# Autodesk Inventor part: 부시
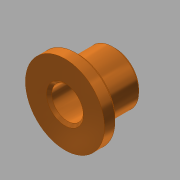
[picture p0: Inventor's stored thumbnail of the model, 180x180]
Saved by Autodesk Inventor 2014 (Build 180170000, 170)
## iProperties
Created: 2016-02
Part Number: 부시
Material: 스테인리스강
Document SubType Name: Modeling
Designer: mduedu
Density: 8.08 g/cm^3
Appearance: 금속 1600F 열
Mass: 45.9536 g
Surface Area: 31.3929 cm^2
Volume: 5.68733 cm^3
Author: mduedu
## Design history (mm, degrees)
sketch "스케치1"
  geometry: C1 r 15 at (0, 0); 1 further point
  constraints: 1 centre point, 1 coincident
  dimensions: "d0" = 30 diameter of C1
extrude "돌출1" new body sketch "스케치1" distance "d1" = 5; taper "d2" = 0 deg
sketch "스케치2"
  geometry: C1 r 10 at (0, 0); 1 further point
  constraints: 1 centre point, 1 coincident
  dimensions: "d3" = 20 diameter of C1
extrude "돌출2" join sketch "스케치2" distance "d4" = 14; taper "d5" = 0 deg
hole "구멍1" diameter "d8" = 12; stored, may be unused: countersink angle "d12" = 90 deg, drill point angle "d14" = 118 deg; dims "d9" = 6, "d10" = 4, "d11" = 2, "d13" = 8, "d15" = 10, "d16" = 10
chamfer "모따기1" distance "d17" = 1; stored, may be unused: second distance "d18" = 2, angle "d19" = 45 deg
chamfer "모따기2" distance "d20" = 1; stored, may be unused: second distance "d21" = 2, angle "d22" = 45 deg
chamfer "모따기3" distance "d23" = 1; stored, may be unused: second distance "d24" = 2, angle "d25" = 45 deg
node "솔리드1"
